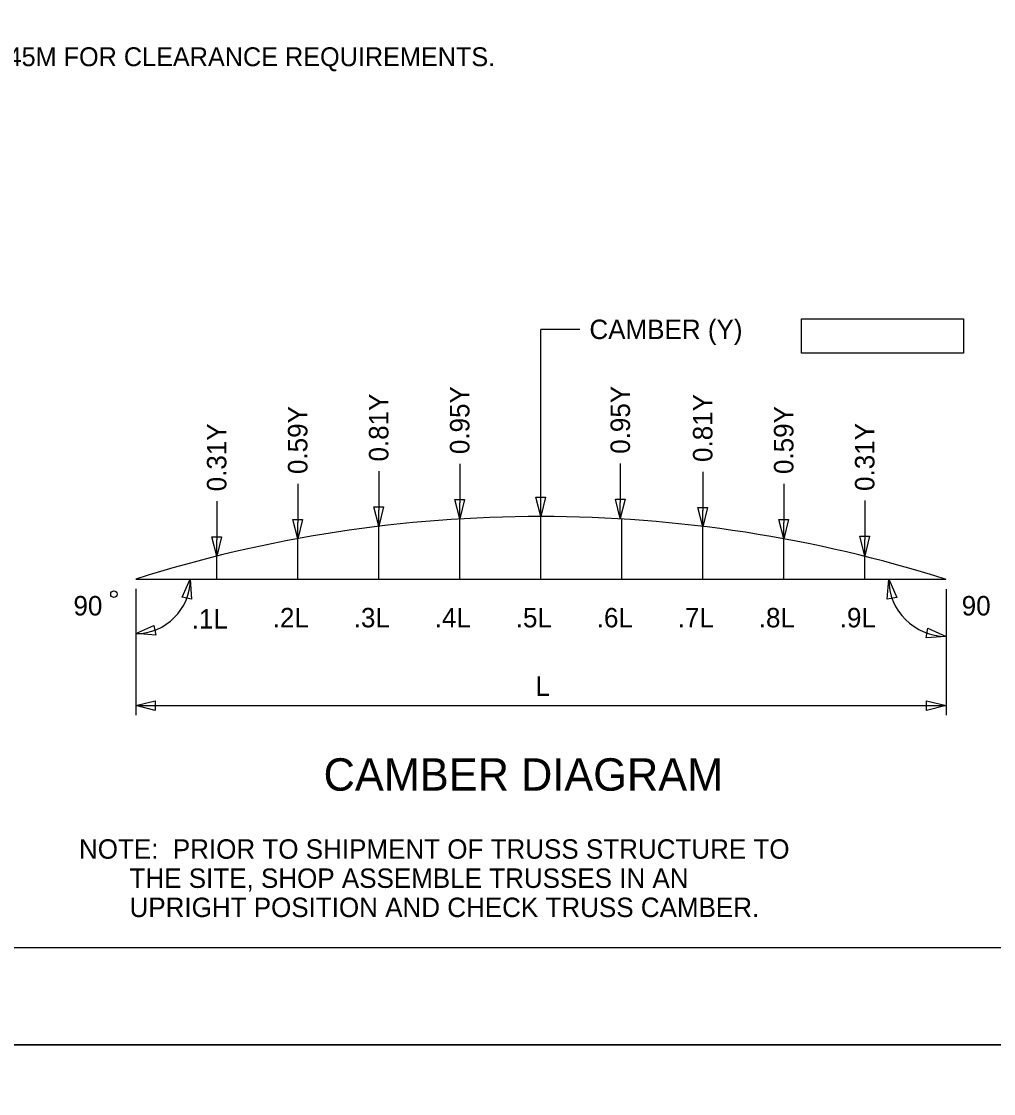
# Model space of a CAD drawing. Extents: x 3831399 to 3833095, y 499014 to 500202.
# Drawn here: x 3832471.3 to 3832621.3, y 499600.5 to 499766 of the extents above; entities that cross this region are included whole.
import ezdxf

# ---------------------------------------------------------------- set-up
doc = ezdxf.new("R2010")
doc.units = 0
for name, color, linetype in [('2', 7, 'Continuous'), ('Default', 7, 'Continuous'), ('DIM TXT', 7, 'Continuous'), ('PLT-BNDY', 7, 'Continuous')]:
    doc.layers.add(name, color=color, linetype=linetype)

msp = doc.modelspace()

# ---------------------------------------------------------------- linework, layer by layer
at = {"layer": '2'}
msp.add_line((3833066.16, 499623.03), (3832280.16, 499623.03), dxfattribs=at)
at = {"layer": 'Default'}
for p, q in [((3832591.65, 499720.04), (3832616.65, 499720.04)), ((3832591.65, 499714.79), (3832591.65, 499720.04)), ((3832616.65, 499720.04), (3832616.65, 499714.79)), ((3832616.65, 499714.79), (3832591.65, 499714.79))]:
    msp.add_line(p, q, dxfattribs=at)
msp.add_circle((3832485.54, 499677.57), 0.502, dxfattribs=at)
at = {"layer": 'DIM TXT'}
for p, q in [((3832551.39, 499689.56), (3832551.41, 499718.44)), ((3832557.41, 499718.44), (3832551.41, 499718.44)), ((3832538.89, 499697.69), (3832538.89, 499691.69)), ((3832563.67, 499697.74), (3832563.67, 499691.74)), ((3832526.39, 499696.55), (3832526.39, 499690.55)), ((3832576.39, 499696.48), (3832576.39, 499690.48)), ((3832513.89, 499694.62), (3832513.89, 499688.62)), ((3832588.89, 499694.62), (3832588.89, 499688.62)), ((3832501.39, 499691.95), (3832501.39, 499685.95)), ((3832526.39, 499688.05), (3832526.39, 499690.55)), ((3832538.89, 499689.19), (3832538.89, 499691.69)), ((3832563.67, 499689.24), (3832563.67, 499691.74)), ((3832576.39, 499687.98), (3832576.39, 499690.48)), ((3832601.39, 499692.01), (3832601.39, 499686.01)), ((3832538.89, 499679.92), (3832538.89, 499689.19)), ((3832551.39, 499679.92), (3832551.39, 499689.56)), ((3832563.89, 499679.92), (3832563.89, 499689.18)), ((3832513.89, 499686.12), (3832513.89, 499688.62)), ((3832526.39, 499679.92), (3832526.39, 499688.05)), ((3832576.39, 499679.92), (3832576.39, 499688.04)), ((3832588.89, 499686.12), (3832588.89, 499688.62)), ((3832501.39, 499683.45), (3832501.39, 499685.95)), ((3832513.89, 499679.92), (3832513.89, 499686.15)), ((3832588.89, 499679.92), (3832588.89, 499686.12)), ((3832601.39, 499683.51), (3832601.39, 499686.01)), ((3832501.39, 499679.92), (3832501.39, 499683.45)), ((3832601.39, 499679.92), (3832601.39, 499683.42)), ((3832488.89, 499679.92), (3832613.89, 499679.92)), ((3832488.89, 499679.92), (3832501.39, 499679.92)), ((3832488.89, 499678.42), (3832488.89, 499658.89)), ((3832613.95, 499678.36), (3832613.95, 499658.89)), ((3832488.89, 499660.39), (3832613.95, 499660.39))]:
    msp.add_line(p, q, dxfattribs=at)
for points in [[(3832539.64, 499692.19), (3832538.89, 499689.19), (3832538.14, 499692.19)], [(3832552.14, 499692.56), (3832551.39, 499689.56), (3832550.64, 499692.56)], [(3832564.42, 499692.24), (3832563.67, 499689.24), (3832562.92, 499692.24)], [(3832527.14, 499691.05), (3832526.39, 499688.05), (3832525.64, 499691.05)], [(3832577.14, 499690.98), (3832576.39, 499687.98), (3832575.64, 499690.98)], [(3832514.64, 499689.12), (3832513.89, 499686.12), (3832513.14, 499689.12)], [(3832589.64, 499689.12), (3832588.89, 499686.12), (3832588.14, 499689.12)], [(3832502.14, 499686.45), (3832501.39, 499683.45), (3832500.64, 499686.45)], [(3832602.14, 499686.51), (3832601.39, 499683.51), (3832600.64, 499686.51)], [(3832496.05, 499677.1), (3832497.32, 499679.92), (3832497.53, 499676.83)], [(3832604.87, 499676.83), (3832605.1, 499679.92), (3832606.35, 499677.09)], [(3832491.98, 499671.28), (3832488.89, 499671.49), (3832491.71, 499672.76)], [(3832611.12, 499672.32), (3832613.95, 499671.07), (3832610.87, 499670.84)], [(3832491.89, 499659.64), (3832488.89, 499660.39), (3832491.89, 499661.14)], [(3832610.95, 499661.14), (3832613.95, 499660.39), (3832610.95, 499659.64)]]:
    msp.add_lwpolyline(points, close=True, dxfattribs=at)
for centre, radius, start, end in [((3832551.33, 499482.59), 206.97, 72.3877, 107.5589), ((3832488.89, 499679.92), 8.43, 270, 360), ((3832613.95, 499679.92), 8.85, 180, 270)]:
    msp.add_arc(centre, radius, start, end, dxfattribs=at)
at = {"layer": 'PLT-BNDY'}
for points in [[(3832240.16, 500202.03), (3833081.16, 500202.03), (3833081.16, 499608.03), (3832240.16, 499608.03)], [(3832240.16, 499608.03), (3833081.16, 499608.03), (3833081.16, 499014.03), (3832240.16, 499014.03)]]:
    msp.add_lwpolyline(points, close=True, dxfattribs=at)

# ---------------------------------------------------------------- texts
at = {"layer": 'DIM TXT'}
for s, height, p in [('SEE BC-745M FOR CLEARANCE REQUIREMENTS.', 2.9099, (3832451.39, 499759.05)), ('CAMBER (Y)', 3, (3832558.91, 499716.94)), ('90', 3, (3832479.29, 499674.3)), ('90', 3, (3832616.36, 499674.3)), ('.1L', 3, (3832497.54, 499672.27)), ('.2L', 3, (3832510.04, 499672.46)), ('.3L', 3, (3832522.54, 499672.46)), ('.4L', 3, (3832535.04, 499672.46)), ('.5L', 3, (3832547.54, 499672.46)), ('.6L', 3, (3832560.04, 499672.46)), ('.7L', 3, (3832572.54, 499672.46)), ('.8L', 3, (3832585.04, 499672.46)), ('.9L', 3, (3832597.54, 499672.46)), ('L', 3, (3832550.57, 499661.89)), ('CAMBER DIAGRAM', 4.9999, (3832517.89, 499647.26)), ('NOTE:  PRIOR TO SHIPMENT OF TRUSS STRUCTURE TO', 2.9999, (3832480.14, 499636.76)), ('       THE SITE, SHOP ASSEMBLE TRUSSES IN AN', 2.9999, (3832480.14, 499632.26)), ('       UPRIGHT POSITION AND CHECK TRUSS CAMBER.', 2.9999, (3832480.14, 499627.76))]:
    msp.add_text(s, height=height, dxfattribs=at).set_placement(p)
for s, p in [('0.95Y', (3832540.39, 499699.19)), ('0.95Y', (3832565.17, 499699.24)), ('0.81Y', (3832527.89, 499698.05)), ('0.81Y', (3832577.89, 499697.98)), ('0.59Y', (3832515.39, 499696.12)), ('0.59Y', (3832590.39, 499696.12)), ('0.31Y', (3832502.89, 499693.45)), ('0.31Y', (3832602.89, 499693.51))]:
    msp.add_text(s, height=3, rotation=90, dxfattribs=at).set_placement(p)

doc.saveas('drawing.dxf')
